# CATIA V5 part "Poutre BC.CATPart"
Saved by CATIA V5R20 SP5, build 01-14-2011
Part number: Poutre BC
Bounding box of the stored display mesh (mm): x 15 to 20, y 39.196 to 167.212, z 61.937 to 99.274
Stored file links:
  F:\iao fini\Poutre BC.CATPart
  F:\iao fini\iao-finipbgliss.CATProduct
  F:\iao fini\poutre CD.CATPart
  F:\iao fini\bielle1.CATPart
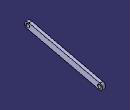
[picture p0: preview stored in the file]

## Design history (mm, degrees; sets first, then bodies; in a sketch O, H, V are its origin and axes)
Set1
  Sketch1 on face of DatumSurface1, origin (5, 0, 0), H (0, 1, 0), V (0, 0, 1)
    circle A1 centre (162.215, 66.933) radius 2.902
    point P1 (162.215, 66.933)
    reference projected point E1 (162.215, 66.933) from Point1
    arc A2 centre (162.215, 66.933) radius 5 from (161.1073, 62.0573) to (163.3418, 71.8044) ccw
    point P2 (162.215, 66.933)
    reference projected point E2 (162.215, 66.933) from Point1
    circle A3 centre (44.192, 94.318) radius 2.902
    point P3 (44.192, 94.318)
    reference projected point E3 (44.192, 94.318) from Point2
    arc A4 centre (44.192, 94.318) radius 5 from (46.1867, 98.9029) to (43.0619, 89.4474) ccw
    point P4 (44.192, 94.318)
    reference projected point E4 (44.192, 94.318) from Point2
    line L1 (46.1867, 98.9029) -> (163.3418, 71.8044)
    line L2 (161.1073, 62.0573) -> (43.0619, 89.4474)
    radius A1 = 2.902
    radius A2 = 5
    radius A4 = 5
    radius A3 = 2.902
    coincidence: P1 E1, P2 E2, P3 E3, P4 E4
    tangency: L1 A2, L2 A4
Set2
  Plane1 "plan profil": linked copy from another document
  DatumSurface1: linked copy from another document
  Point1 "C": linked copy from another document
  Point2 "B": linked copy from another document
Body1 (main body)
  Pad1: profile Sketch1, direction (1, 0, 0), length 15, opposite side length -10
